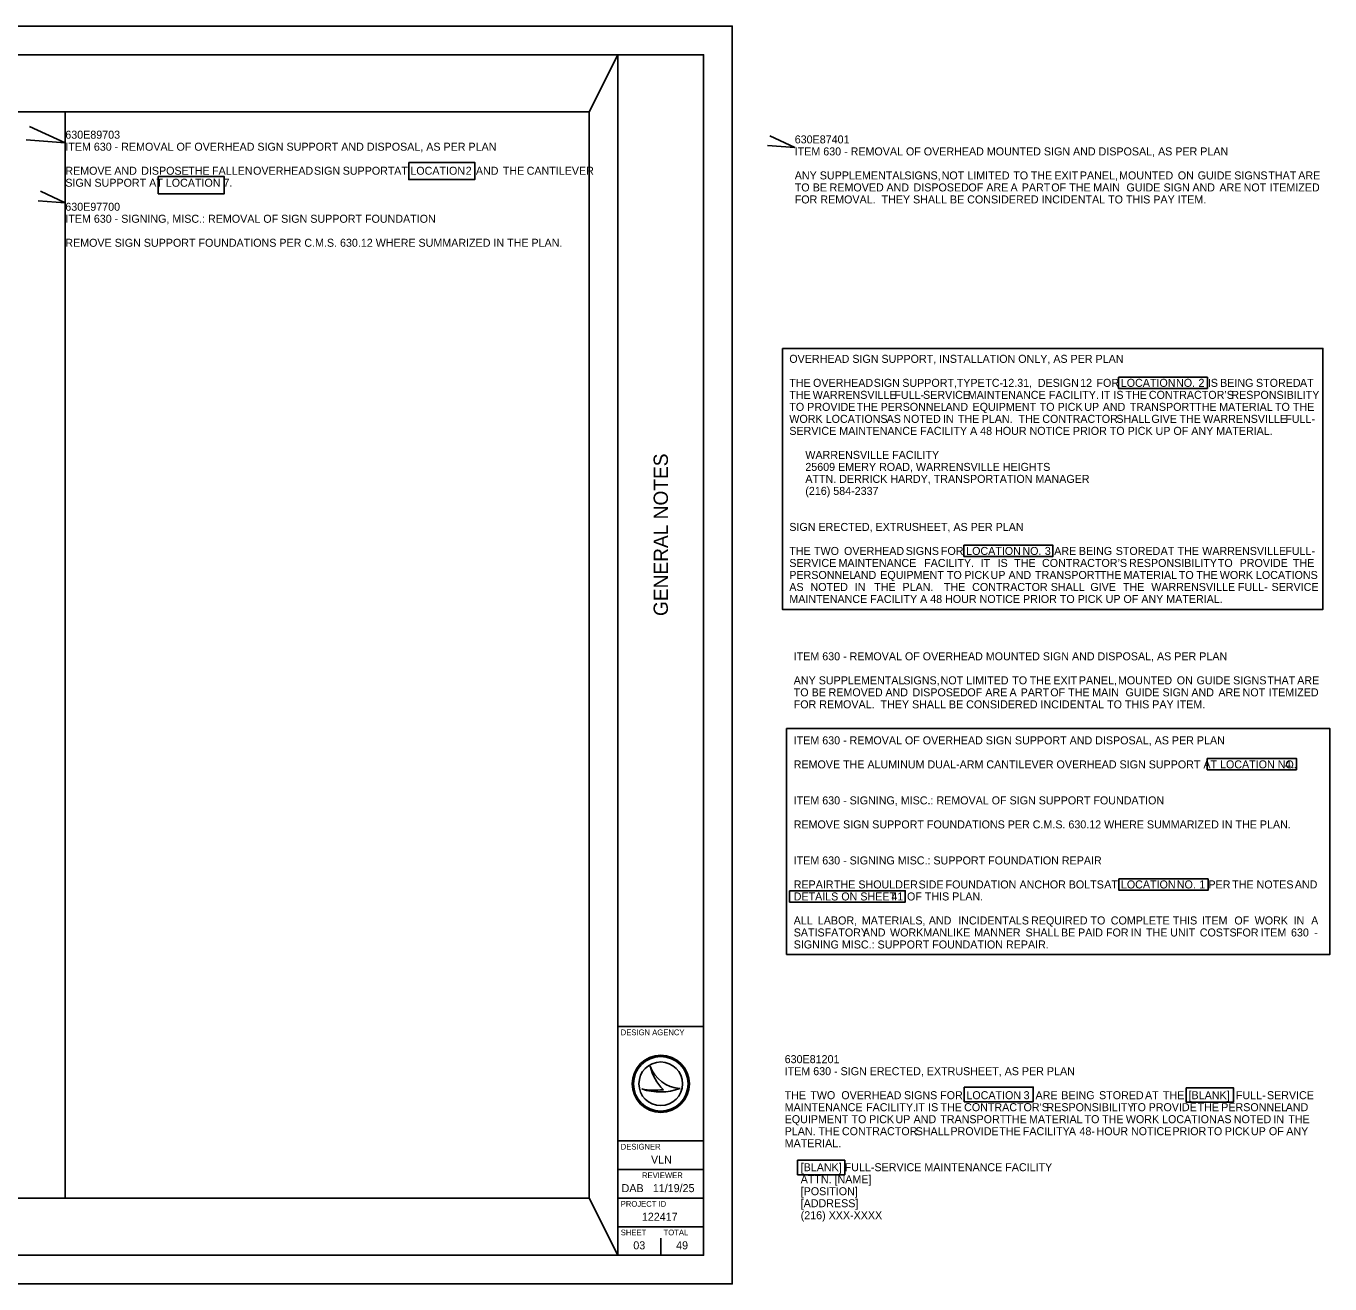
# Model space of a CAD drawing. Extents: x -1.5 to 44.5, y 0 to 22.
# Drawn here: x 21.65 to 44.46, y 0 to 22 of the extents above; entities that cross this region are included whole.
import ezdxf

# ---------------------------------------------------------------- set-up
doc = ezdxf.new("R2010")
doc.units = 0
for name, color, linetype in [('SC_Scratch1', 7, 'Continuous'), ('SH_Border', 7, 'Continuous'), ('SH_Cut_Line', 7, 'Continuous'), ('SH_Data', 7, 'Continuous'), ('SH_Text', 7, 'Continuous')]:
    doc.layers.add(name, color=color, linetype=linetype)

msp = doc.modelspace()

# ---------------------------------------------------------------- linework, layer by layer
at = {"layer": 'SC_Scratch1'}
for p, q in [((31.5, 20.5), (32, 21.5)), ((31.5, 20.5), (2, 20.5)), ((22.333, 1.5), (22.333, 20.5)), ((31.5, 20.5), (31.5, 1.5)), ((2, 1.5), (31.5, 1.5)), ((31.5, 1.5), (32, 0.5))]:
    msp.add_line(p, q, dxfattribs=at)
for points in [[(21.709, 20.246), (22.333, 19.96), (21.65, 20.012)], [(34.657, 20.079), (35.094, 19.878), (34.619, 19.914)], [(21.896, 19.111), (22.333, 18.91), (21.858, 18.946)], [(21.896, 19.111), (22.333, 18.91), (21.858, 18.946)]]:
    msp.add_lwpolyline(points, dxfattribs=at)
for points in [[(28.342, 19.615), (29.496, 19.615), (29.496, 19.316), (28.342, 19.316)], [(23.959, 19.368), (25.113, 19.368), (25.113, 19.068), (23.959, 19.068)]]:
    msp.add_lwpolyline(points, close=True, dxfattribs=at)
at = {"layer": 'SH_Border'}
for p, q in [((32, 0.5), (32, 21.5)), ((32, 4.5), (33.5, 4.5)), ((32, 2.5), (33.5, 2.5)), ((32, 2), (33.5, 2)), ((32, 1.5), (33.5, 1.5)), ((32, 1), (33.5, 1))]:
    msp.add_line(p, q, dxfattribs=at)
msp.add_lwpolyline([(1.5, 21.5), (33.5, 21.5), (33.5, 0.5), (1.5, 0.5)], close=True, dxfattribs=at)
at = {"layer": 'SH_Cut_Line'}
msp.add_lwpolyline([(0, 0), (34, 0), (34, 22), (0, 22)], close=True, dxfattribs=at)
at = {"layer": 'SH_Data'}
for p, q in [((32.567, 3.81), (32.567, 3.81)), ((32.75, 3.5), (32.75, 3.5)), ((32.417, 3.41), (32.417, 3.41)), ((33.087, 3.419), (33.087, 3.419)), ((32.75, 0.5), (32.75, 0.8)), ((32.375, 0.675), (32.375, 0.675))]:
    msp.add_line(p, q, dxfattribs=at)
for radius in [0.5, 0.477, 0.477, 0.382]:
    msp.add_circle((32.75, 3.5), radius, dxfattribs=at)
for centre, radius, start, end in [((33.116, 3.998), 0.58, 198.9257, 198.9319), ((33.347, 3.97), 0.796, 191.6379, 191.6421), ((33.116, 3.998), 0.58, 198.9319, 267.1657), ((33.347, 3.97), 0.796, 191.6421, 226.0947), ((32.739, 4.37), 1.013, 251.4576, 290.0832), ((32.648, 4.654), 1.266, 259.4964, 259.4995), ((32.739, 4.37), 1.013, 251.4527, 251.4576), ((32.648, 4.654), 1.266, 259.4995, 276.6672)]:
    msp.add_arc(centre, radius, start, end, dxfattribs=at)
at = {"layer": 'SH_Text'}
for points in [[(34.877, 16.361), (44.335, 16.361), (44.335, 11.797), (34.877, 11.797)], [(40.755, 15.859), (42.313, 15.859), (42.313, 15.662), (40.755, 15.662)], [(38.053, 12.921), (39.611, 12.921), (39.611, 12.724), (38.053, 12.724)], [(34.951, 9.712), (44.457, 9.712), (44.457, 5.762), (34.951, 5.762)], [(42.31, 9.19), (43.871, 9.19), (43.871, 8.993), (42.31, 8.993)], [(40.765, 7.083), (42.326, 7.083), (42.326, 6.886), (40.765, 6.886)], [(35.004, 6.877), (37.028, 6.877), (37.028, 6.679), (35.004, 6.679)], [(38.059, 3.442), (39.266, 3.442), (39.266, 3.187), (38.059, 3.187)], [(41.943, 3.431), (42.769, 3.431), (42.769, 3.176), (41.943, 3.176)], [(35.143, 2.163), (35.969, 2.163), (35.969, 1.908), (35.143, 1.908)]]:
    msp.add_lwpolyline(points, close=True, dxfattribs=at)

# ---------------------------------------------------------------- texts
at = {"layer": 'SC_Scratch1'}
for s, p in [('630E89703', (22.333, 20.03)), ('630E87401', (35.094, 19.948)), ('630E97700', (22.333, 18.77)), ('630E81201', (34.918, 3.861))]:
    msp.add_text(s, height=0.14, dxfattribs=at).set_placement(p)
at = {"layer": 'SH_Data'}
msp.add_text('GENERAL NOTES', height=0.25, rotation=90, dxfattribs=at).set_placement((32.875, 11.682))
for s, height, p in [('DESIGN AGENCY', 0.1, (32.05, 4.35)), ('DESIGNER', 0.1, (32.05, 2.35)), ('VLN', 0.14, (32.579, 2.105)), ('REVIEWER', 0.1, (32.422, 1.85)), ('DAB', 0.14, (32.065, 1.605)), ('11/19/25', 0.14, (32.611, 1.605)), ('PROJECT ID', 0.1, (32.05, 1.35)), ('122417', 0.14, (32.42, 1.105)), ('SHEET', 0.1, (32.05, 0.85)), ('TOTAL', 0.1, (32.8, 0.85)), ('03', 0.14, (32.27, 0.605)), ('49', 0.14, (33.019, 0.605))]:
    msp.add_text(s, height=height, dxfattribs=at).set_placement(p)
at = {"layer": 'SH_Text'}
for s, p in [('ITEM 630 - REMOVAL OF OVERHEAD SIGN SUPPORT AND DISPOSAL, AS PER PLAN', (22.333, 19.82)), ('ITEM 630 - REMOVAL OF OVERHEAD MOUNTED SIGN AND DISPOSAL, AS PER PLAN', (35.094, 19.738)), ('REMOVE ', (22.333, 19.4)), ('AND ', (23.189, 19.4)), ('DISPOSE ', (23.66, 19.4)), ('THE ', (24.482, 19.4)), ('FALLEN ', (24.9, 19.4)), ('OVERHEAD ', (25.618, 19.4)), ('SIGN ', (26.683, 19.4)), ('SUPPORT ', (27.186, 19.4)), ('AT ', (28.086, 19.4)), ('LOCATION ', (28.369, 19.4)), ('2 ', (29.338, 19.4)), ('AND ', (29.515, 19.4)), ('THE ', (29.986, 19.4)), ('CANTILEVER ', (30.404, 19.4)), ('ANY ', (35.094, 19.318)), ('SUPPLEMENTAL ', (35.532, 19.318)), ('SIGNS, ', (37.012, 19.318)), ('NOT ', (37.664, 19.318)), ('LIMITED ', (38.113, 19.318)), ('TO ', (38.917, 19.318)), ('THE ', (39.223, 19.318)), ('EXIT ', (39.636, 19.318)), ('PANEL, ', (40.082, 19.318)), ('MOUNTED ', (40.768, 19.318)), ('ON ', (41.796, 19.318)), ('GUIDE ', (42.143, 19.318)), ('SIGNS ', (42.783, 19.318)), ('THAT ', (43.38, 19.318)), ('ARE ', (43.902, 19.318)), ('SIGN SUPPORT AT LOCATION 7. ', (22.333, 19.19)), ('TO ', (35.094, 19.108)), ('BE ', (35.409, 19.108)), ('REMOVED ', (35.704, 19.108)), ('AND ', (36.698, 19.108)), ('DISPOSED ', (37.172, 19.108)), ('OF ', (38.132, 19.108)), ('ARE ', (38.446, 19.108)), ('A ', (38.869, 19.108)), ('PART ', (39.065, 19.108)), ('OF ', (39.582, 19.108)), ('THE ', (39.896, 19.108)), ('MAIN ', (40.316, 19.108)), ('GUIDE ', (40.898, 19.108)), ('SIGN ', (41.546, 19.108)), ('AND ', (42.051, 19.108)), ('ARE ', (42.524, 19.108)), ('NOT ', (42.947, 19.108)), ('ITEMIZED ', (43.404, 19.108)), ('FOR REMOVAL.  THEY SHALL BE CONSIDERED INCIDENTAL TO THIS PAY ITEM.', (35.094, 18.898)), ('ITEM 630 - SIGNING, MISC.: REMOVAL OF SIGN SUPPORT FOUNDATION', (22.333, 18.56)), ('REMOVE SIGN SUPPORT FOUNDATIONS PER C.M.S. 630.12 WHERE SUMMARIZED IN THE PLAN.  ', (22.333, 18.14)), ('OVERHEAD SIGN SUPPORT, INSTALLATION ONLY, AS PER PLAN', (34.999, 16.11)), ('THE ', (34.999, 15.69)), ('OVERHEAD ', (35.414, 15.69)), ('SIGN ', (36.476, 15.69)), ('SUPPORT, ', (36.975, 15.69)), ('TYPE ', (37.928, 15.69)), ('TC-', (38.427, 15.69)), ('12.31, ', (38.726, 15.69)), ('DESIGN ', (39.346, 15.69)), ('12 ', (40.087, 15.69)), ('FOR ', (40.373, 15.69)), ('LOCATION ', (40.798, 15.69)), ('NO. ', (41.765, 15.69)), ('2', (42.157, 15.69)), (' IS ', (42.269, 15.69)), ('BEING ', (42.536, 15.69)), ('STORED ', (43.163, 15.69)), ('AT ', (43.933, 15.69)), ('THE ', (34.999, 15.48)), ('WARRENSVILLE ', (35.408, 15.48)), ('FULL-', (36.837, 15.48)), ('SERVICE ', (37.339, 15.48)), ('MAINTENANCE ', (38.121, 15.48)), ('FACILITY.  ', (39.541, 15.48)), ('IT ', (40.45, 15.48)), ('IS ', (40.669, 15.48)), ('THE ', (40.88, 15.48)), ('CONTRACTOR’S ', (41.289, 15.48)), ('RESPONSIBILITY ', (42.732, 15.48)), ('TO ', (34.999, 15.27)), ('PROVIDE ', (35.312, 15.27)), ('THE ', (36.177, 15.27)), ('PERSONNEL ', (36.597, 15.27)), ('AND ', (37.731, 15.27)), ('EQUIPMENT ', (38.204, 15.27)), ('TO ', (39.379, 15.27)), ('PICK ', (39.693, 15.27)), ('UP ', (40.159, 15.27)), ('AND ', (40.482, 15.27)), ('TRANSPORT ', (40.955, 15.27)), ('THE ', (42.099, 15.27)), ('MATERIAL ', (42.519, 15.27)), ('TO ', (43.495, 15.27)), ('THE ', (43.809, 15.27)), ('WORK ', (34.999, 15.06)), ('LOCATIONS ', (35.635, 15.06)), ('AS ', (36.702, 15.06)), ('NOTED ', (36.993, 15.06)), ('IN ', (37.687, 15.06)), ('THE ', (37.948, 15.06)), ('PLAN.  ', (38.364, 15.06)), ('THE ', (39.009, 15.06)), ('CONTRACTOR ', (39.425, 15.06)), ('SHALL ', (40.72, 15.06)), ('GIVE ', (41.333, 15.06)), ('THE ', (41.824, 15.06)), ('WARRENSVILLE ', (42.239, 15.06)), ('FULL-', (43.676, 15.06)), ('SERVICE MAINTENANCE FACILITY A 48 HOUR NOTICE PRIOR TO PICK UP OF ANY MATERIAL.', (34.999, 14.85)), ('WARRENSVILLE FACILITY', (35.279, 14.43)), ('ATTN. DERRICK HARDY, TRANSPORTATION MANAGER', (35.279, 14.01)), ('25609 EMERY ROAD, WARRENSVILLE HEIGHTS', (35.279, 14.22)), ('(216) 584-2337', (35.279, 13.8)), ('SIGN ERECTED, EXTRUSHEET, AS PER PLAN', (34.999, 13.17)), ('THE ', (34.999, 12.75)), ('TWO ', (35.431, 12.75)), ('OVERHEAD ', (35.956, 12.75)), ('SIGNS ', (37.035, 12.75)), ('FOR ', (37.651, 12.75)), ('LOCATION ', (38.093, 12.75)), ('NO. ', (39.077, 12.75)), ('3', (39.469, 12.75)), (' ARE ', (39.581, 12.75)), ('BEING ', (40.065, 12.75)), ('STORED ', (40.709, 12.75)), ('AT ', (41.495, 12.75)), ('THE ', (41.791, 12.75)), ('WARRENSVILLE ', (42.223, 12.75)), ('FULL-', (43.676, 12.75)), ('SERVICE ', (34.999, 12.54)), ('MAINTENANCE ', (35.859, 12.54)), ('FACILITY.  ', (37.358, 12.54)), ('IT ', (38.345, 12.54)), ('IS ', (38.643, 12.54)), ('THE ', (38.933, 12.54)), ('CONTRACTOR’S ', (39.42, 12.54)), ('RESPONSIBILITY ', (40.941, 12.54)), ('TO ', (42.496, 12.54)), ('PROVIDE ', (42.877, 12.54)), ('THE ', (43.809, 12.54)), ('PERSONNEL ', (34.999, 12.33)), ('AND ', (36.125, 12.33)), ('EQUIPMENT ', (36.59, 12.33)), ('TO ', (37.756, 12.33)), ('PICK ', (38.061, 12.33)), ('UP ', (38.52, 12.33)), ('AND ', (38.834, 12.33)), ('TRANSPORT ', (39.298, 12.33)), ('THE ', (40.435, 12.33)), ('MATERIAL ', (40.846, 12.33)), ('TO ', (41.814, 12.33)), ('THE ', (42.119, 12.33)), ('WORK ', (42.53, 12.33)), ('LOCATIONS ', (43.162, 12.33)), ('AS ', (34.999, 12.12)), ('NOTED ', (35.369, 12.12)), ('IN ', (36.143, 12.12)), ('THE ', (36.484, 12.12)), ('PLAN.  ', (36.979, 12.12)), ('THE ', (37.703, 12.12)), ('CONTRACTOR ', (38.198, 12.12)), ('SHALL ', (39.573, 12.12)), ('GIVE ', (40.266, 12.12)), ('THE ', (40.836, 12.12)), ('WARRENSVILLE ', (41.331, 12.12)), ('FULL-', (42.847, 12.12)), ('SERVICE ', (43.436, 12.12)), ('MAINTENANCE FACILITY A 48 HOUR NOTICE PRIOR TO PICK UP OF ANY MATERIAL. ', (34.999, 11.91)), ('ITEM 630 - REMOVAL OF OVERHEAD MOUNTED SIGN AND DISPOSAL, AS PER PLAN', (35.076, 10.907)), ('ANY ', (35.076, 10.487)), ('SUPPLEMENTAL ', (35.514, 10.487)), ('SIGNS, ', (36.994, 10.487)), ('NOT ', (37.646, 10.487)), ('LIMITED ', (38.095, 10.487)), ('TO ', (38.899, 10.487)), ('THE ', (39.205, 10.487)), ('EXIT ', (39.618, 10.487)), ('PANEL, ', (40.064, 10.487)), ('MOUNTED ', (40.749, 10.487)), ('ON ', (41.777, 10.487)), ('GUIDE ', (42.124, 10.487)), ('SIGNS ', (42.764, 10.487)), ('THAT ', (43.361, 10.487)), ('ARE ', (43.884, 10.487)), ('TO ', (35.076, 10.277)), ('BE ', (35.39, 10.277)), ('REMOVED ', (35.686, 10.277)), ('AND ', (36.68, 10.277)), ('DISPOSED ', (37.154, 10.277)), ('OF ', (38.114, 10.277)), ('ARE ', (38.428, 10.277)), ('A ', (38.851, 10.277)), ('PART ', (39.046, 10.277)), ('OF ', (39.564, 10.277)), ('THE ', (39.877, 10.277)), ('MAIN ', (40.298, 10.277)), ('GUIDE ', (40.88, 10.277)), ('SIGN ', (41.528, 10.277)), ('AND ', (42.033, 10.277)), ('ARE ', (42.506, 10.277)), ('NOT ', (42.929, 10.277)), ('ITEMIZED ', (43.385, 10.277)), ('FOR REMOVAL.  THEY SHALL BE CONSIDERED INCIDENTAL TO THIS PAY ITEM.', (35.076, 10.067)), ('ITEM 630 - REMOVAL OF OVERHEAD SIGN SUPPORT AND DISPOSAL, AS PER PLAN', (35.076, 9.437)), ('REMOVE THE ALUMINUM DUAL-ARM CANTILEVER OVERHEAD SIGN SUPPORT AT LOCATION NO. ', (35.076, 9.017)), ('4', (43.67, 9.017)), ('. ', (43.781, 9.017)), ('ITEM 630 - SIGNING, MISC.: REMOVAL OF SIGN SUPPORT FOUNDATION', (35.076, 8.387)), ('REMOVE SIGN SUPPORT FOUNDATIONS PER C.M.S. 630.12 WHERE SUMMARIZED IN THE PLAN.  ', (35.076, 7.967)), ('ITEM 630 - SIGNING MISC.: SUPPORT FOUNDATION REPAIR', (35.076, 7.337)), ('REPAIR ', (35.076, 6.917)), ('DETAILS ON SHEET', (35.076, 6.707)), ('THE ', (35.781, 6.917)), ('SHOULDER ', (36.207, 6.917)), (' 41', (36.733, 6.707)), (' OF THIS PLAN. ', (37.006, 6.707)), ('SIDE ', (37.26, 6.917)), ('FOUNDATION ', (37.733, 6.917)), ('ANCHOR ', (39.026, 6.917)), ('BOLTS ', (39.887, 6.917)), ('AT ', (40.508, 6.917)), ('LOCATION ', (40.8, 6.917)), ('NO. ', (41.778, 6.917)), ('1 ', (42.17, 6.917)), ('PER ', (42.332, 6.917)), ('THE ', (42.747, 6.917)), ('NOTES ', (43.174, 6.917)), ('AND ', (43.842, 6.917)), ('ALL ', (35.076, 6.287)), ('LABOR, ', (35.498, 6.287)), ('MATERIALS, ', (36.267, 6.287)), ('AND ', (37.439, 6.287)), ('INCIDENTALS ', (37.954, 6.287)), ('REQUIRED ', (39.228, 6.287)), ('TO ', (40.268, 6.287)), ('COMPLETE ', (40.623, 6.287)), ('THIS ', (41.708, 6.287)), ('ITEM ', (42.217, 6.287)), ('OF ', (42.785, 6.287)), ('WORK ', (43.14, 6.287)), ('IN ', (43.822, 6.287)), ('A ', (44.128, 6.287)), ('SATISFATORY ', (35.076, 6.077)), ('AND ', (36.286, 6.077)), ('WORKMANLIKE ', (36.761, 6.077)), ('MANNER ', (38.234, 6.077)), ('SHALL ', (39.132, 6.077)), ('BE ', (39.752, 6.077)), ('PAID ', (40.05, 6.077)), ('FOR ', (40.539, 6.077)), ('IN ', (40.972, 6.077)), ('THE ', (41.24, 6.077)), ('UNIT ', (41.663, 6.077)), ('COSTS ', (42.18, 6.077)), ('FOR ', (42.813, 6.077)), ('ITEM ', (43.247, 6.077)), ('630 ', (43.776, 6.077)), ('SIGNING MISC.: SUPPORT FOUNDATION REPAIR.', (35.076, 5.867)), ('- ', (44.182, 6.077)), ('ITEM 630 - SIGN ERECTED, EXTRUSHEET, AS PER PLAN', (34.918, 3.651)), ('THE ', (34.918, 3.231)), ('TWO ', (35.366, 3.231)), ('OVERHEAD ', (35.909, 3.231)), ('SIGNS ', (37.005, 3.231)), ('FOR ', (37.638, 3.231)), ('LOCATION ', (38.097, 3.231)), ('3 ', (39.098, 3.231)), ('ARE ', (39.306, 3.231)), ('BEING ', (39.757, 3.231)), ('STORED ', (40.418, 3.231)), ('AT ', (41.222, 3.231)), ('THE ', (41.535, 3.231)), ('[BLANK] ', (41.984, 3.231)), ('FULL-', (42.812, 3.231)), ('SERVICE ', (43.355, 3.231)), ('MAINTENANCE ', (34.918, 3.021)), ('FACILITY. ', (36.342, 3.021)), ('IT ', (37.205, 3.021)), ('IS ', (37.428, 3.021)), ('THE ', (37.644, 3.021)), ("CONTRACTOR'S ", (38.057, 3.021)), ('RESPONSIBILITY ', (39.498, 3.021)), ('TO ', (40.978, 3.021)), ('PROVIDE ', (41.285, 3.021)), ('THE ', (42.142, 3.021)), ('PERSONNEL ', (42.555, 3.021)), ('AND ', (43.683, 3.021)), ('EQUIPMENT ', (34.918, 2.811)), ('PLAN. ', (34.918, 2.601)), ('THE ', (35.508, 2.601)), ('CONTRACTOR ', (35.919, 2.601)), ('TO ', (36.087, 2.811)), ('PICK ', (36.395, 2.811)), ('UP ', (36.856, 2.811)), ('AND ', (37.173, 2.811)), ('SHALL ', (37.209, 2.601)), ('TRANSPORT ', (37.64, 2.811)), ('PROVIDE ', (37.818, 2.601)), ('THE ', (38.673, 2.601)), ('THE ', (38.779, 2.811)), ('FACILITY ', (39.084, 2.601)), ('MATERIAL ', (39.193, 2.811)), ('A ', (39.889, 2.601)), ('48-', (40.075, 2.601)), ('TO ', (40.164, 2.811)), ('HOUR ', (40.374, 2.601)), ('THE ', (40.471, 2.811)), ('WORK ', (40.886, 2.811)), ('NOTICE ', (40.976, 2.601)), ('LOCATION ', (41.52, 2.811)), ('PRIOR ', (41.701, 2.601)), ('TO ', (42.313, 2.601)), ('AS ', (42.486, 2.811)), ('PICK ', (42.617, 2.601)), ('NOTED ', (42.775, 2.811)), ('UP ', (43.075, 2.601)), ('OF ', (43.389, 2.601)), ('IN ', (43.468, 2.811)), ('ANY ', (43.693, 2.601)), ('THE ', (43.728, 2.811)), ('MATERIAL. ', (34.918, 2.391)), ('[BLANK] FULL-SERVICE MAINTENANCE FACILITY', (35.198, 1.971)), ('ATTN. [NAME]', (35.198, 1.761)), ('[POSITION]', (35.198, 1.551)), ('[ADDRESS]', (35.198, 1.341)), ('(216) XXX-XXXX', (35.198, 1.131))]:
    msp.add_text(s, height=0.14, dxfattribs=at).set_placement(p)

doc.saveas('drawing.dxf')
